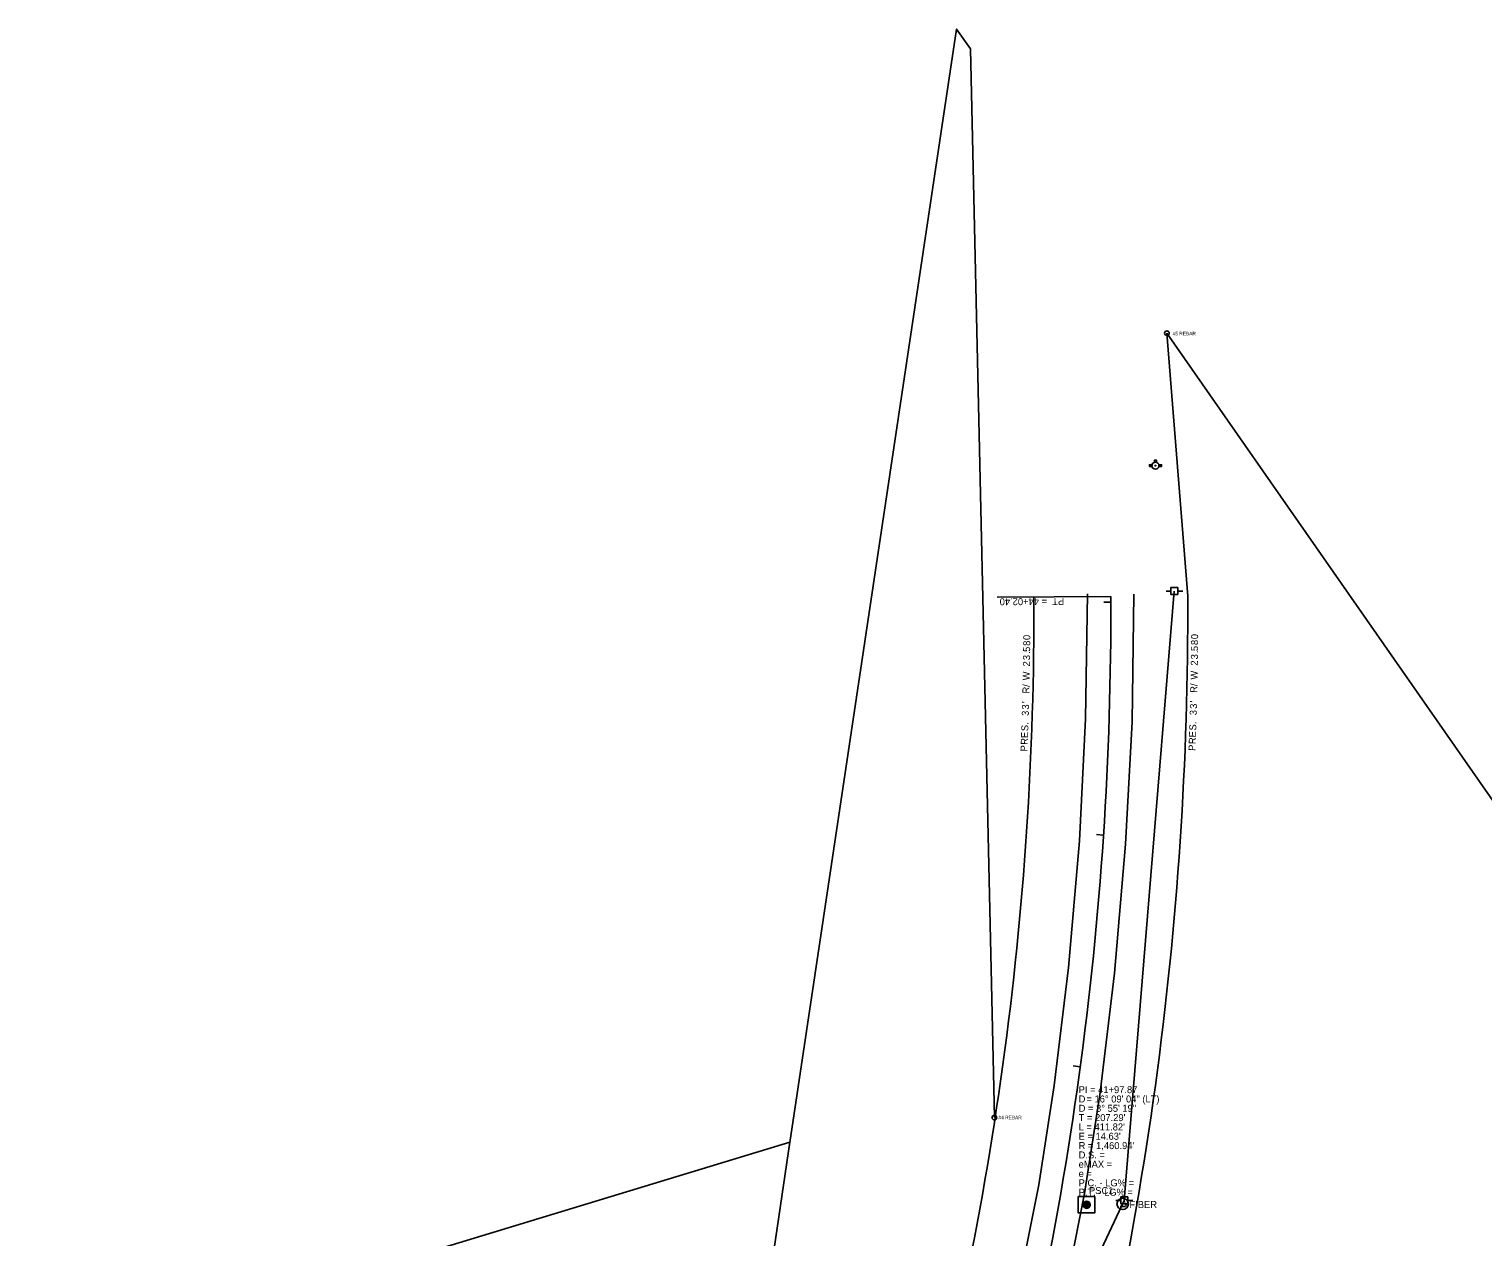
# Model space of a CAD drawing. Extents: x 1618707 to 1620612, y 1189955 to 1192629.
# Drawn here: x 1619365 to 1619988, y 1192110 to 1192629 of the extents above; entities that cross this region are included whole.
import ezdxf

# ---------------------------------------------------------------- set-up
doc = ezdxf.new("R2010")
doc.units = 0
for name, color, linetype in [('RD_EX_DV_Prop', 7, 'Continuous'), ('RD_EX_DV_Prop_txCode', 7, 'Continuous'), ('RD_EX_DV_PropPin', 7, 'Continuous'), ('RD_EX_Road', 7, 'Continuous'), ('RD_EX_RW', 7, 'Continuous'), ('RD_EX_RW_TX', 7, 'Continuous'), ('RD_EX_UT', 7, 'Continuous'), ('RD_HC_Cl', 7, 'Continuous'), ('RD_HC_Data', 7, 'Continuous'), ('RD_HC_Data_Tic', 7, 'Continuous'), ('RD_HC_Survey', 7, 'Continuous'), ('RD_HC_Survey_txCode', 7, 'Continuous'), ('RD_TX_Utilities', 7, 'Continuous')]:
    doc.layers.add(name, color=color, linetype=linetype)

msp = doc.modelspace()

# ---------------------------------------------------------------- linework, layer by layer
at = {"layer": 'RD_EX_DV_Prop'}
for p, q in [((1619778.88, 1192161.5), (1619768.55, 1192620.2)), ((1619861.78, 1192385.25), (1619852.88, 1192498.17)), ((1619852.88, 1192498.17), (1619852.88, 1192498.17)), ((1619852.88, 1192498.17), (1620612.09, 1191408.03))]:
    msp.add_line(p, q, dxfattribs=at)
for points in [[(1619768.56, 1192620.21), (1619762.66, 1192628.67), (1619691.13, 1192150.77)], [(1618953.32, 1191926.47), (1619691.12, 1192151), (1619618.45, 1191657.59)]]:
    msp.add_lwpolyline(points, dxfattribs=at)
at = {"layer": 'RD_EX_DV_PropPin'}
for centre in [(1619852.88, 1192498.17), (1619778.88, 1192161.5)]:
    msp.add_circle(centre, 1, dxfattribs=at)
at = {"layer": 'RD_EX_Road'}
for points in [[(1619818.78, 1192386.23), (1619818.01, 1192332.67), (1619815.33, 1192280.25), (1619810.62, 1192225.96), (1619804.57, 1192175.23), (1619797.92, 1192132.69), (1619787.4, 1192079.58), (1619774.13, 1192023.21), (1619760.61, 1191972.59), (1619744.83, 1191917.11), (1619738.12, 1191891.42), (1619730.55, 1191865.86), (1619717.53, 1191819.93), (1619712.78, 1191803.93), (1619701.26, 1191765.6), (1619687.27, 1191726.81)], [(1619838.66, 1192386.16), (1619838.03, 1192331.37), (1619835.13, 1192278.82), (1619830.44, 1192223.56), (1619824.24, 1192172.25), (1619817.51, 1192128.89), (1619806.84, 1192074.51), (1619793.17, 1192017.72), (1619779.48, 1191967.35), (1619763.64, 1191911.17), (1619749.44, 1191860.79), (1619736.49, 1191814), (1619721.43, 1191759.35), (1619712.05, 1191719.7)]]:
    msp.add_lwpolyline(points, dxfattribs=at)
at = {"layer": 'RD_EX_RW'}
for radius in [1493.94, 1427.94]:
    msp.add_arc((1618367.86, 1192378.61), radius, 344.10357, 0.2547, dxfattribs=at)
at = {"layer": 'RD_EX_UT'}
for p, q in [((1619852.49, 1192387.48), (1619854.54, 1192387.48)), ((1619856.04, 1192387.51), (1619856.04, 1192387.51)), ((1619857.54, 1192387.48), (1619859.68, 1192387.48)), ((1619831.02, 1192125.96), (1619833.08, 1192125.96)), ((1619832.81, 1192123.36), (1619835.13, 1192123.36)), ((1619834.58, 1192125.99), (1619834.58, 1192125.99)), ((1619836.08, 1192125.96), (1619838.22, 1192125.96))]:
    msp.add_line(p, q, dxfattribs=at)
for points in [[(1619846.48, 1192440.97), (1619845.35, 1192440.97), (1619845.35, 1192441.72), (1619846.51, 1192441.72), (1619846.47, 1192441.52), (1619846.45, 1192441.24)], [(1619847.61, 1192442.75), (1619847.61, 1192443.7), (1619848.36, 1192443.7), (1619848.36, 1192442.73), (1619848.17, 1192442.77), (1619847.91, 1192442.79), (1619847.78, 1192442.78)], [(1619849.42, 1192440.97), (1619850.59, 1192440.97), (1619850.59, 1192441.72), (1619849.39, 1192441.72), (1619849.43, 1192441.51), (1619849.45, 1192441.27)], [(1619854.54, 1192386.01), (1619854.54, 1192389.01), (1619857.54, 1192389.01), (1619857.54, 1192386.01)], [(1619833.08, 1192124.49), (1619833.08, 1192127.49), (1619836.08, 1192127.49), (1619836.08, 1192124.49)]]:
    msp.add_lwpolyline(points, close=True, dxfattribs=at)
for points in [[(1619846.48, 1192440.97), (1619845.35, 1192440.97)], [(1619856.04, 1192387.51), (1619834.58, 1192125.99), (1619723.01, 1191888.05)]]:
    msp.add_lwpolyline(points, dxfattribs=at)
for centre, radius in [((1619847.95, 1192441.29), 1.5), ((1619847.95, 1192441.29), 0.187), ((1619833.88, 1192124.46), 2.45)]:
    msp.add_circle(centre, radius, dxfattribs=at)
at = {"layer": 'RD_HC_Cl'}
msp.add_arc((1618367.86, 1192378.61), 1460.94, 344.10357, 0.2547, dxfattribs=at)
at = {"layer": 'RD_HC_Data'}
msp.add_line((1619828.78, 1192385.1), (1619780.12, 1192384.89), dxfattribs=at)
at = {"layer": 'RD_HC_Data_Tic'}
for p, q in [((1619828.79, 1192382.7), (1619825.79, 1192382.69)), ((1619825.65, 1192282.77), (1619822.65, 1192282.96)), ((1619815.68, 1192183.29), (1619812.7, 1192183.69))]:
    msp.add_line(p, q, dxfattribs=at)
at = {"layer": 'RD_HC_Survey'}
for p, q in [((1619816.88, 1192123.74), (1619816.88, 1192124.46)), ((1619816.93, 1192123.57), (1619816.93, 1192124.63)), ((1619816.98, 1192123.45), (1619816.98, 1192124.75)), ((1619817.03, 1192123.35), (1619817.03, 1192124.85)), ((1619817.08, 1192123.27), (1619817.08, 1192124.94)), ((1619817.13, 1192123.19), (1619817.13, 1192125.01)), ((1619817.18, 1192123.13), (1619817.18, 1192125.07)), ((1619817.23, 1192123.07), (1619817.23, 1192125.13)), ((1619817.28, 1192123.01), (1619817.28, 1192125.19)), ((1619817.33, 1192122.97), (1619817.33, 1192125.24)), ((1619817.38, 1192122.92), (1619817.38, 1192125.28)), ((1619817.43, 1192122.88), (1619817.43, 1192125.32)), ((1619817.48, 1192122.84), (1619817.48, 1192125.36)), ((1619817.53, 1192122.81), (1619817.53, 1192125.39)), ((1619817.58, 1192122.78), (1619817.58, 1192125.43)), ((1619817.63, 1192122.75), (1619817.63, 1192125.46)), ((1619817.68, 1192122.72), (1619817.68, 1192125.48)), ((1619817.73, 1192122.69), (1619817.73, 1192125.51)), ((1619817.78, 1192122.67), (1619817.78, 1192125.53)), ((1619817.83, 1192122.65), (1619817.83, 1192125.55)), ((1619817.88, 1192122.63), (1619817.88, 1192125.57)), ((1619817.93, 1192122.62), (1619817.93, 1192125.59)), ((1619817.98, 1192122.6), (1619817.98, 1192125.6)), ((1619818.03, 1192122.59), (1619818.03, 1192125.61)), ((1619818.08, 1192122.58), (1619818.08, 1192125.62)), ((1619818.13, 1192122.57), (1619818.13, 1192125.63)), ((1619818.18, 1192122.56), (1619818.18, 1192125.64)), ((1619818.23, 1192122.55), (1619818.23, 1192125.65)), ((1619818.28, 1192122.55), (1619818.28, 1192125.65)), ((1619818.33, 1192122.55), (1619818.33, 1192125.65)), ((1619818.38, 1192122.55), (1619818.38, 1192125.66)), ((1619818.43, 1192122.55), (1619818.43, 1192125.66)), ((1619818.48, 1192122.55), (1619818.48, 1192125.65)), ((1619818.53, 1192122.55), (1619818.53, 1192125.65)), ((1619818.58, 1192122.56), (1619818.58, 1192125.64)), ((1619818.63, 1192122.56), (1619818.63, 1192125.64)), ((1619818.68, 1192122.57), (1619818.68, 1192125.63)), ((1619818.73, 1192122.58), (1619818.73, 1192125.62)), ((1619818.78, 1192122.6), (1619818.78, 1192125.61)), ((1619818.83, 1192122.61), (1619818.83, 1192125.59)), ((1619818.88, 1192122.63), (1619818.88, 1192125.58)), ((1619818.93, 1192122.64), (1619818.93, 1192125.56)), ((1619818.98, 1192122.66), (1619818.98, 1192125.54)), ((1619819.03, 1192122.68), (1619819.03, 1192125.52)), ((1619819.08, 1192122.71), (1619819.08, 1192125.5)), ((1619819.13, 1192122.73), (1619819.13, 1192125.47)), ((1619819.18, 1192122.76), (1619819.18, 1192125.44)), ((1619819.23, 1192122.79), (1619819.23, 1192125.41)), ((1619819.28, 1192122.83), (1619819.28, 1192125.38)), ((1619819.33, 1192122.86), (1619819.33, 1192125.34)), ((1619819.38, 1192122.9), (1619819.38, 1192125.3)), ((1619819.43, 1192122.94), (1619819.43, 1192125.26)), ((1619819.48, 1192122.99), (1619819.48, 1192125.21)), ((1619819.53, 1192123.04), (1619819.53, 1192125.16)), ((1619819.58, 1192123.1), (1619819.58, 1192125.1)), ((1619819.63, 1192123.16), (1619819.63, 1192125.04)), ((1619819.68, 1192123.23), (1619819.68, 1192124.97)), ((1619819.73, 1192123.31), (1619819.73, 1192124.89)), ((1619819.78, 1192123.4), (1619819.78, 1192124.8)), ((1619819.83, 1192123.51), (1619819.83, 1192124.69)), ((1619819.88, 1192123.65), (1619819.88, 1192124.55)), ((1619819.93, 1192123.88), (1619819.93, 1192124.33))]:
    msp.add_line(p, q, dxfattribs=at)
msp.add_lwpolyline([(1619821.93, 1192127.64), (1619814.86, 1192127.64), (1619814.86, 1192120.57), (1619821.93, 1192120.57)], close=True, dxfattribs=at)
msp.add_circle((1619818.4, 1192124.1), 1.55, dxfattribs=at)

# ---------------------------------------------------------------- texts
at = {"layer": 'RD_EX_DV_Prop_txCode'}
for s, p in [('#5 REBAR', (1619855.28, 1192497.24)), ('#4 REBAR', (1619780.6, 1192160.8))]:
    msp.add_text(s, height=1.5, dxfattribs=at).set_placement(p)
at = {"layer": 'RD_EX_RW_TX'}
for s, rotation, p in [('0', 89.56945, (1619794.24, 1192366.45)), ('8', 89.50803, (1619866.22, 1192364.3)), ('0', 89.60397, (1619866.25, 1192366.81)), ('8', 89.46888, (1619794.22, 1192363.95)), ('5', 89.36451, (1619794.19, 1192361.35)), ('.', 89.33225, (1619794.18, 1192360.54)), ('3', 89.27272, (1619866.15, 1192358.15)), ('5', 89.40848, (1619866.2, 1192361.7)), ('.', 89.37771, (1619866.19, 1192360.89)), ('2', 89.11402, (1619794.1, 1192355.11)), ('3', 89.22218, (1619794.14, 1192357.8)), ('2', 89.16955, (1619866.11, 1192355.45)), ('W', 88.87396, (1619793.99, 1192349.14)), ('/', 88.83377, (1619865.95, 1192346.67)), ('W', 88.94057, (1619866.01, 1192349.46)), ('/', 88.762, (1619793.93, 1192346.35)), ('R', 88.64624, (1619793.86, 1192343.47)), ('R', 88.72336, (1619865.89, 1192343.78)), ('3', 88.26007, (1619793.59, 1192333.86)), ('3', 88.37014, (1619793.67, 1192336.6)), ("'", 88.4802, (1619793.75, 1192339.34)), ('3', 88.355, (1619865.63, 1192334.15)), ('3', 88.45999, (1619865.71, 1192336.9)), ("'", 88.56497, (1619865.79, 1192339.64)), ('S', 87.99725, (1619793.37, 1192327.32)), ('.', 88.10731, (1619793.47, 1192330.06)), ('S', 88.1043, (1619865.42, 1192327.6)), ('.', 88.20929, (1619865.52, 1192330.34)), ('R', 87.76194, (1619793.15, 1192321.46)), ('E', 87.87769, (1619793.26, 1192324.34)), ('R', 87.87985, (1619865.21, 1192321.73)), ('E', 87.99027, (1619865.32, 1192324.62)), ('P', 87.64618, (1619793.03, 1192318.58)), ('P', 87.76943, (1619865.1, 1192318.85))]:
    msp.add_text(s, height=3, rotation=rotation, dxfattribs=at).set_placement(p)
at = {"layer": 'RD_EX_UT'}
msp.add_text('W', height=3, dxfattribs=at).set_placement((1619832.65, 1192123.46))
at = {"layer": 'RD_HC_Data'}
msp.add_text('PT  = 44+02.40', height=3, rotation=180.2547, dxfattribs=at).set_placement((1619808.78, 1192384.51))
for s, p in [('PI = 41+97.87', (1619815, 1192172)), ('D', (1619815, 1192168)), ('D = 3%%d 55\' 19"', (1619815, 1192164)), ('   = 16%%d 09\' 04" (LT)', (1619815, 1192168)), ("T = 207.29'", (1619815, 1192160)), ("L = 411.82'", (1619815, 1192156)), ("E = 14.63'", (1619815, 1192152)), ("R = 1,460.94'", (1619815, 1192148)), ('eMAX = ', (1619815, 1192140)), ('D.S. = ', (1619815, 1192144)), ('e = ', (1619815, 1192136)), ('P.C. - LG% = ', (1619815, 1192132)), ('P.T. - LG% = ', (1619815, 1192128))]:
    msp.add_text(s, height=3, dxfattribs=at).set_placement(p)
at = {"layer": 'RD_HC_Survey_txCode'}
msp.add_text('PSC1', height=3, dxfattribs=at).set_placement((1619819.43, 1192128.69))
at = {"layer": 'RD_TX_Utilities'}
msp.add_text('FIBER', height=3, dxfattribs=at).set_placement((1619836.82, 1192122.71))

doc.saveas('drawing.dxf')
